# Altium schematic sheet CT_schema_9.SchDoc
size 274 x 160 mm
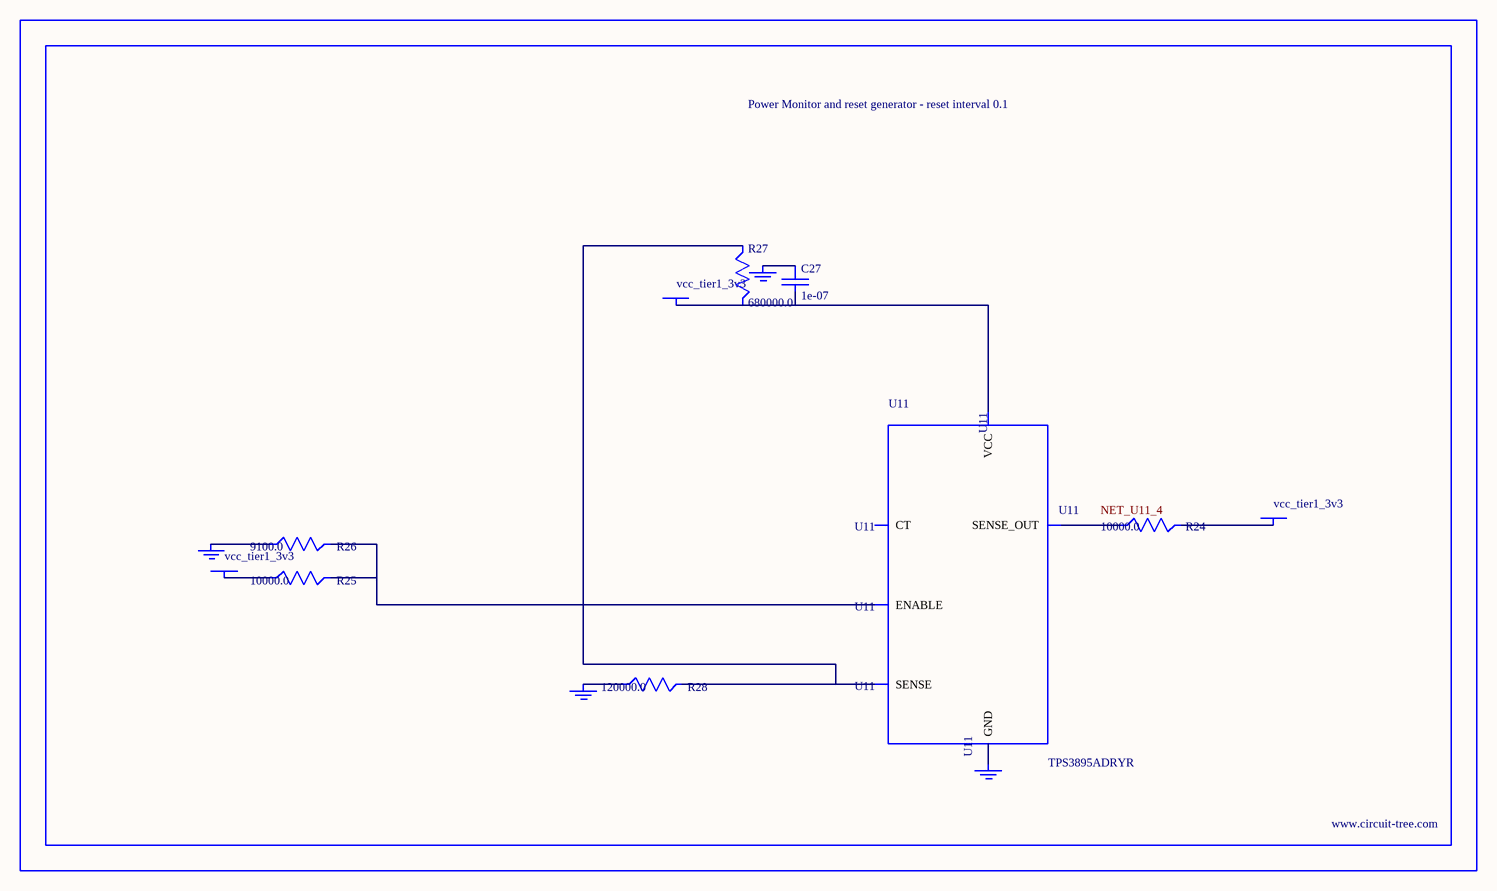
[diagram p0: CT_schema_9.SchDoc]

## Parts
BORDER8  (no value)
C27  1e-07  [C0402]
GND_INSTANCE_8_0  (no value)
GND_INSTANCE_8_1  (no value)
GND_INSTANCE_8_2  (no value)
GND_INSTANCE_8_3  (no value)
POWER_INSTANCE_8_0  vcc_tier1_3v3
POWER_INSTANCE_8_1  vcc_tier1_3v3
POWER_INSTANCE_8_2  vcc_tier1_3v3
R24  10000.0  [R0603]
R25  10000.0  [R0603]
R26  9100.0  [R0603]
R27  680000.0  [R0603]
R28  120000.0  [R0603]
U11  TPS3895ADRYR  [SON-6]

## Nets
NetC27_1: C27.1 GND_INSTANCE_8_2.0(GND)
NetC27_2: C27.2 POWER_INSTANCE_8_2.0(PWR) R27.2 U11.6(VCC)
NetGND_INSTANCE_8_0_0: GND_INSTANCE_8_0.0(GND) R26.1
NetGND_INSTANCE_8_1_0: GND_INSTANCE_8_1.0(GND) R28.1
NetGND_INSTANCE_8_3_0: GND_INSTANCE_8_3.0(GND) U11.2(GND)
NetPOWER_INSTANCE_8_0_0: POWER_INSTANCE_8_0.0(PWR) R25.1
NetPOWER_INSTANCE_8_1_0: POWER_INSTANCE_8_1.0(PWR) R24.2
NetR24_1: R24.1 U11.4(SENSE_OUT)
NetR25_2: R25.2 R26.2 U11.1(ENABLE)
NetR27_1: R27.1 R28.2 U11.3(SENSE)

Not connected (* = marked no-connect by the designer): U11 5(CT)

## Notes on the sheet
- Labels drawn without touching a wire or pin: NET_U11_4

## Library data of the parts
BORDER8 = BORDER_PAGE8
C27 = C0402C104K3RACTU
GND_INSTANCE_8_0-GND_INSTANCE_8_3 = GND
POWER_INSTANCE_8_0-POWER_INSTANCE_8_2 = PWR
R24 R25 = RC0603JR-0710KL
R26 = RC0603JR-079K1L
R27 = RC0603JR-07680KL
R28 = RC0603JR-07120KL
